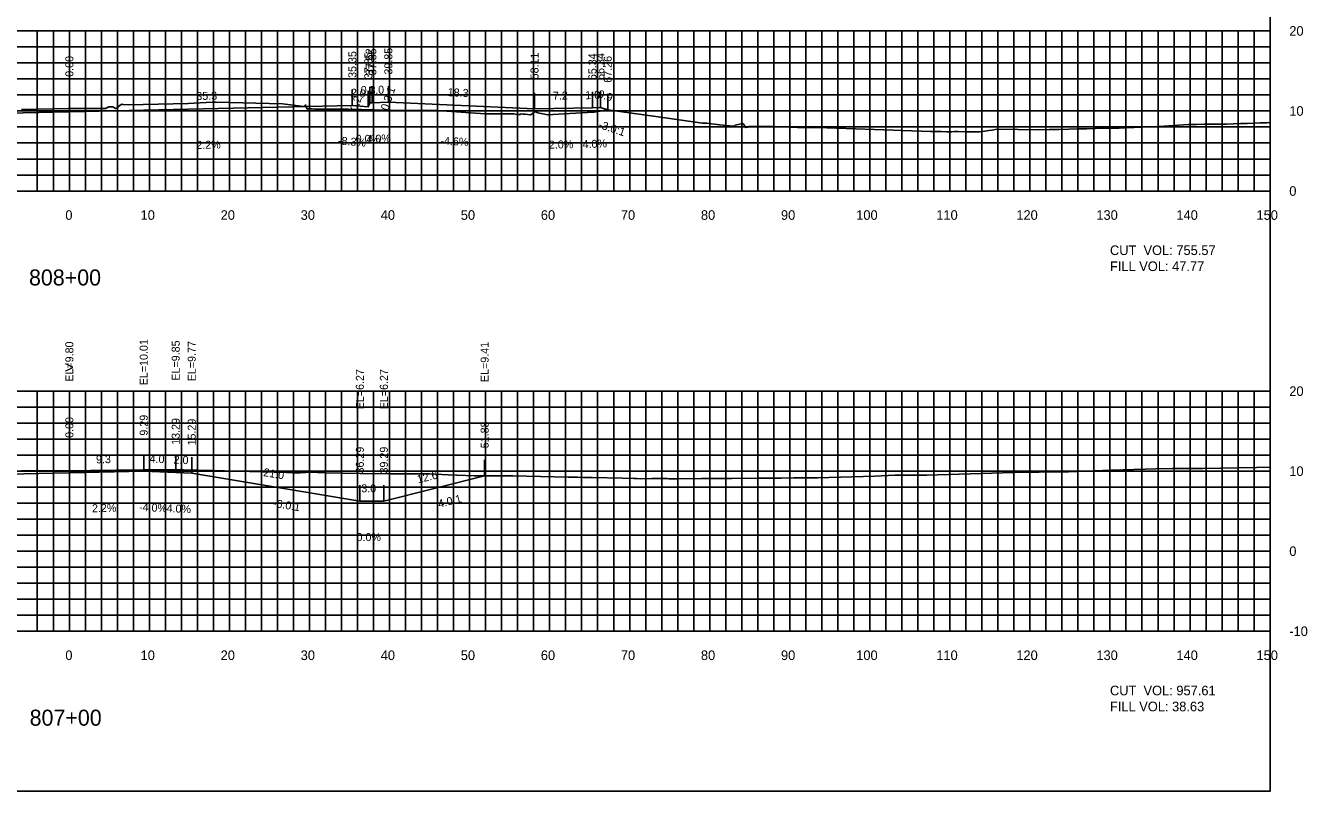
# Model space of a CAD drawing. Extents: x 1797419 to 1809236, y 248759 to 251512.
# Drawn here: x 1803985.5 to 1804145.7, y 250417.3 to 250512.9 of the extents above; entities that cross this region are included whole.
import ezdxf

# ---------------------------------------------------------------- set-up
doc = ezdxf.new("R2010")
doc.units = 0
for name, color, linetype in [('1', 7, 'Continuous'), ('10', 7, 'Continuous'), ('3', 7, 'Continuous'), ('31', 7, 'Continuous'), ('4', 7, 'Continuous'), ('60', 7, 'Continuous'), ('ANNO-TXT', 7, 'Continuous'), ('CL-CNST', 7, 'Continuous'), ('Level 62', 7, 'Continuous'), ('M-ROADS', 7, 'Continuous')]:
    doc.layers.add(name, color=color, linetype=linetype)

msp = doc.modelspace()

# ---------------------------------------------------------------- linework, layer by layer
for p, q in [((1804030.85, 250503.36), (1804030.85, 250505.36)), ((1803991, 250502.17), (1803991, 250504.17)), ((1804026.35, 250502.94), (1804026.35, 250504.94)), ((1804028.35, 250502.78), (1804028.35, 250504.78)), ((1804028.52, 250503.28), (1804028.52, 250505.28)), ((1804028.85, 250503.28), (1804028.85, 250505.28)), ((1804049.11, 250502.51), (1804049.11, 250504.51)), ((1804056.34, 250502.66), (1804056.34, 250504.66)), ((1804057.34, 250502.7), (1804057.34, 250504.7)), ((1804058.26, 250502.39), (1804058.26, 250504.39)), ((1803991, 250457.06), (1803991, 250459.06)), ((1804000.29, 250457.26), (1804000.29, 250459.26)), ((1804004.29, 250457.1), (1804004.29, 250459.1)), ((1804006.29, 250457.02), (1804006.29, 250459.02)), ((1804042.88, 250456.67), (1804042.88, 250458.67)), ((1804027.29, 250453.52), (1804027.29, 250455.52)), ((1804030.29, 250453.52), (1804030.29, 250455.52))]:
    msp.add_line(p, q)
msp.add_lwpolyline([(1803841, 250417.26), (1804141, 250417.26), (1804141, 250607.26), (1803841, 250607.26)], close=True)
at = {"layer": '60'}
for p, q in [((1804141, 250492.26), (1804141, 250512.26)), ((1804141.06, 250512.26), (1804141, 250512.26)), ((1804141.06, 250502.26), (1804141, 250502.26)), ((1803841, 250492.26), (1804141, 250492.26)), ((1803991, 250492.2), (1803991, 250492.26)), ((1804001, 250492.2), (1804001, 250492.26)), ((1804011, 250492.2), (1804011, 250492.26)), ((1804021, 250492.2), (1804021, 250492.26)), ((1804031, 250492.2), (1804031, 250492.26)), ((1804041, 250492.2), (1804041, 250492.26)), ((1804051, 250492.2), (1804051, 250492.26)), ((1804061, 250492.2), (1804061, 250492.26)), ((1804071, 250492.2), (1804071, 250492.26)), ((1804081, 250492.2), (1804081, 250492.26)), ((1804091, 250492.2), (1804091, 250492.26)), ((1804101, 250492.2), (1804101, 250492.26)), ((1804111, 250492.2), (1804111, 250492.26)), ((1804121, 250492.2), (1804121, 250492.26)), ((1804131, 250492.2), (1804131, 250492.26)), ((1804141, 250492.2), (1804141, 250492.26)), ((1804141.06, 250492.26), (1804141, 250492.26)), ((1804141, 250437.26), (1804141, 250467.26)), ((1804141.06, 250467.26), (1804141, 250467.26)), ((1804141.06, 250457.26), (1804141, 250457.26)), ((1804141.06, 250447.26), (1804141, 250447.26)), ((1803841, 250437.26), (1804141, 250437.26)), ((1803991, 250437.2), (1803991, 250437.26)), ((1804001, 250437.2), (1804001, 250437.26)), ((1804011, 250437.2), (1804011, 250437.26)), ((1804021, 250437.2), (1804021, 250437.26)), ((1804031, 250437.2), (1804031, 250437.26)), ((1804041, 250437.2), (1804041, 250437.26)), ((1804051, 250437.2), (1804051, 250437.26)), ((1804061, 250437.2), (1804061, 250437.26)), ((1804071, 250437.2), (1804071, 250437.26)), ((1804081, 250437.2), (1804081, 250437.26)), ((1804091, 250437.2), (1804091, 250437.26)), ((1804101, 250437.2), (1804101, 250437.26)), ((1804111, 250437.2), (1804111, 250437.26)), ((1804121, 250437.2), (1804121, 250437.26)), ((1804131, 250437.2), (1804131, 250437.26)), ((1804141, 250437.2), (1804141, 250437.26)), ((1804141.06, 250437.26), (1804141, 250437.26))]:
    msp.add_line(p, q, dxfattribs=at)
at = {"layer": 'CL-CNST'}
for points in [[(1803897.88, 250503.68), (1803905.42, 250501.17), (1803913.42, 250500.85), (1803913.75, 250500.85), (1803913.91, 250500.35), (1803915.91, 250500.51), (1803991, 250502.17), (1804026.35, 250502.94), (1804028.35, 250502.78), (1804028.52, 250503.28), (1804028.85, 250503.28), (1804030.85, 250503.36), (1804049.11, 250502.51), (1804056.34, 250502.66), (1804057.34, 250502.7), (1804058.26, 250502.39)], [(1803879.92, 250457), (1803900, 250451.98), (1803903, 250451.98), (1803924, 250455.48), (1803926, 250455.56), (1803930, 250455.72), (1803991, 250457.06), (1804000.29, 250457.26), (1804004.29, 250457.1), (1804006.29, 250457.02), (1804027.29, 250453.52), (1804030.29, 250453.52), (1804042.88, 250456.67)]]:
    msp.add_lwpolyline(points, dxfattribs=at)
at = {"layer": 'Level 62'}
for p, q in [((1803841, 250512.26), (1804141, 250512.26)), ((1803987, 250492.26), (1803987, 250512.26)), ((1803989, 250492.26), (1803989, 250512.26)), ((1803991, 250492.26), (1803991, 250512.26)), ((1803993, 250492.26), (1803993, 250512.26)), ((1803995, 250492.26), (1803995, 250512.26)), ((1803997, 250492.26), (1803997, 250512.26)), ((1803999, 250492.26), (1803999, 250512.26)), ((1804001, 250492.26), (1804001, 250512.26)), ((1804003, 250492.26), (1804003, 250512.26)), ((1804005, 250492.26), (1804005, 250512.26)), ((1804007, 250492.26), (1804007, 250512.26)), ((1804009, 250492.26), (1804009, 250512.26)), ((1804011, 250492.26), (1804011, 250512.26)), ((1804013, 250492.26), (1804013, 250512.26)), ((1804015, 250492.26), (1804015, 250512.26)), ((1804017, 250492.26), (1804017, 250512.26)), ((1804019, 250492.26), (1804019, 250512.26)), ((1804021, 250492.26), (1804021, 250512.26)), ((1804023, 250492.26), (1804023, 250512.26)), ((1804025, 250492.26), (1804025, 250512.26)), ((1804027, 250492.26), (1804027, 250512.26)), ((1804029, 250492.26), (1804029, 250512.26)), ((1804031, 250492.26), (1804031, 250512.26)), ((1804033, 250492.26), (1804033, 250512.26)), ((1804035, 250492.26), (1804035, 250512.26)), ((1804037, 250492.26), (1804037, 250512.26)), ((1804039, 250492.26), (1804039, 250512.26)), ((1804041, 250492.26), (1804041, 250512.26)), ((1804043, 250492.26), (1804043, 250512.26)), ((1804045, 250492.26), (1804045, 250512.26)), ((1804047, 250492.26), (1804047, 250512.26)), ((1804049, 250492.26), (1804049, 250512.26)), ((1804051, 250492.26), (1804051, 250512.26)), ((1804053, 250492.26), (1804053, 250512.26)), ((1804055, 250492.26), (1804055, 250512.26)), ((1804057, 250492.26), (1804057, 250512.26)), ((1804059, 250492.26), (1804059, 250512.26)), ((1804061, 250492.26), (1804061, 250512.26)), ((1804063, 250492.26), (1804063, 250512.26)), ((1804065, 250492.26), (1804065, 250512.26)), ((1804067, 250492.26), (1804067, 250512.26)), ((1804069, 250492.26), (1804069, 250512.26)), ((1804071, 250492.26), (1804071, 250512.26)), ((1804073, 250492.26), (1804073, 250512.26)), ((1804075, 250492.26), (1804075, 250512.26)), ((1804077, 250492.26), (1804077, 250512.26)), ((1804079, 250492.26), (1804079, 250512.26)), ((1804081, 250492.26), (1804081, 250512.26)), ((1804083, 250492.26), (1804083, 250512.26)), ((1804085, 250492.26), (1804085, 250512.26)), ((1804087, 250492.26), (1804087, 250512.26)), ((1804089, 250492.26), (1804089, 250512.26)), ((1804091, 250492.26), (1804091, 250512.26)), ((1804093, 250492.26), (1804093, 250512.26)), ((1804095, 250492.26), (1804095, 250512.26)), ((1804097, 250492.26), (1804097, 250512.26)), ((1804099, 250492.26), (1804099, 250512.26)), ((1804101, 250492.26), (1804101, 250512.26)), ((1804103, 250492.26), (1804103, 250512.26)), ((1804105, 250492.26), (1804105, 250512.26)), ((1804107, 250492.26), (1804107, 250512.26)), ((1804109, 250492.26), (1804109, 250512.26)), ((1804111, 250492.26), (1804111, 250512.26)), ((1804113, 250492.26), (1804113, 250512.26)), ((1804115, 250492.26), (1804115, 250512.26)), ((1804117, 250492.26), (1804117, 250512.26)), ((1804119, 250492.26), (1804119, 250512.26)), ((1804121, 250492.26), (1804121, 250512.26)), ((1804123, 250492.26), (1804123, 250512.26)), ((1804125, 250492.26), (1804125, 250512.26)), ((1804127, 250492.26), (1804127, 250512.26)), ((1804129, 250492.26), (1804129, 250512.26)), ((1804131, 250492.26), (1804131, 250512.26)), ((1804133, 250492.26), (1804133, 250512.26)), ((1804135, 250492.26), (1804135, 250512.26)), ((1804137, 250492.26), (1804137, 250512.26)), ((1804139, 250492.26), (1804139, 250512.26)), ((1804141, 250492.26), (1804141, 250512.26)), ((1803841, 250510.26), (1804141, 250510.26)), ((1803841, 250508.26), (1804141, 250508.26)), ((1803841, 250506.26), (1804141, 250506.26)), ((1803841, 250504.26), (1804141, 250504.26)), ((1803841, 250502.26), (1804141, 250502.26)), ((1803841, 250500.26), (1804141, 250500.26)), ((1803841, 250498.26), (1804141, 250498.26)), ((1803841, 250496.26), (1804141, 250496.26)), ((1803841, 250494.26), (1804141, 250494.26)), ((1803841, 250492.26), (1804141, 250492.26)), ((1803841, 250467.26), (1804141, 250467.26)), ((1803987, 250437.26), (1803987, 250467.26)), ((1803989, 250437.26), (1803989, 250467.26)), ((1803991, 250437.26), (1803991, 250467.26)), ((1803993, 250437.26), (1803993, 250467.26)), ((1803995, 250437.26), (1803995, 250467.26)), ((1803997, 250437.26), (1803997, 250467.26)), ((1803999, 250437.26), (1803999, 250467.26)), ((1804001, 250437.26), (1804001, 250467.26)), ((1804003, 250437.26), (1804003, 250467.26)), ((1804005, 250437.26), (1804005, 250467.26)), ((1804007, 250437.26), (1804007, 250467.26)), ((1804009, 250437.26), (1804009, 250467.26)), ((1804011, 250437.26), (1804011, 250467.26)), ((1804013, 250437.26), (1804013, 250467.26)), ((1804015, 250437.26), (1804015, 250467.26)), ((1804017, 250437.26), (1804017, 250467.26)), ((1804019, 250437.26), (1804019, 250467.26)), ((1804021, 250437.26), (1804021, 250467.26)), ((1804023, 250437.26), (1804023, 250467.26)), ((1804025, 250437.26), (1804025, 250467.26)), ((1804027, 250437.26), (1804027, 250467.26)), ((1804029, 250437.26), (1804029, 250467.26)), ((1804031, 250437.26), (1804031, 250467.26)), ((1804033, 250437.26), (1804033, 250467.26)), ((1804035, 250437.26), (1804035, 250467.26)), ((1804037, 250437.26), (1804037, 250467.26)), ((1804039, 250437.26), (1804039, 250467.26)), ((1804041, 250437.26), (1804041, 250467.26)), ((1804043, 250437.26), (1804043, 250467.26)), ((1804045, 250437.26), (1804045, 250467.26)), ((1804047, 250437.26), (1804047, 250467.26)), ((1804049, 250437.26), (1804049, 250467.26)), ((1804051, 250437.26), (1804051, 250467.26)), ((1804053, 250437.26), (1804053, 250467.26)), ((1804055, 250437.26), (1804055, 250467.26)), ((1804057, 250437.26), (1804057, 250467.26)), ((1804059, 250437.26), (1804059, 250467.26)), ((1804061, 250437.26), (1804061, 250467.26)), ((1804063, 250437.26), (1804063, 250467.26)), ((1804065, 250437.26), (1804065, 250467.26)), ((1804067, 250437.26), (1804067, 250467.26)), ((1804069, 250437.26), (1804069, 250467.26)), ((1804071, 250437.26), (1804071, 250467.26)), ((1804073, 250437.26), (1804073, 250467.26)), ((1804075, 250437.26), (1804075, 250467.26)), ((1804077, 250437.26), (1804077, 250467.26)), ((1804079, 250437.26), (1804079, 250467.26)), ((1804081, 250437.26), (1804081, 250467.26)), ((1804083, 250437.26), (1804083, 250467.26)), ((1804085, 250437.26), (1804085, 250467.26)), ((1804087, 250437.26), (1804087, 250467.26)), ((1804089, 250437.26), (1804089, 250467.26)), ((1804091, 250437.26), (1804091, 250467.26)), ((1804093, 250437.26), (1804093, 250467.26)), ((1804095, 250437.26), (1804095, 250467.26)), ((1804097, 250437.26), (1804097, 250467.26)), ((1804099, 250437.26), (1804099, 250467.26)), ((1804101, 250437.26), (1804101, 250467.26)), ((1804103, 250437.26), (1804103, 250467.26)), ((1804105, 250437.26), (1804105, 250467.26)), ((1804107, 250437.26), (1804107, 250467.26)), ((1804109, 250437.26), (1804109, 250467.26)), ((1804111, 250437.26), (1804111, 250467.26)), ((1804113, 250437.26), (1804113, 250467.26)), ((1804115, 250437.26), (1804115, 250467.26)), ((1804117, 250437.26), (1804117, 250467.26)), ((1804119, 250437.26), (1804119, 250467.26)), ((1804121, 250437.26), (1804121, 250467.26)), ((1804123, 250437.26), (1804123, 250467.26)), ((1804125, 250437.26), (1804125, 250467.26)), ((1804127, 250437.26), (1804127, 250467.26)), ((1804129, 250437.26), (1804129, 250467.26)), ((1804131, 250437.26), (1804131, 250467.26)), ((1804133, 250437.26), (1804133, 250467.26)), ((1804135, 250437.26), (1804135, 250467.26)), ((1804137, 250437.26), (1804137, 250467.26)), ((1804139, 250437.26), (1804139, 250467.26)), ((1804141, 250437.26), (1804141, 250467.26)), ((1803841, 250465.26), (1804141, 250465.26)), ((1803841, 250463.26), (1804141, 250463.26)), ((1803841, 250461.26), (1804141, 250461.26)), ((1803841, 250459.26), (1804141, 250459.26)), ((1803841, 250457.26), (1804141, 250457.26)), ((1803841, 250455.26), (1804141, 250455.26)), ((1803841, 250453.26), (1804141, 250453.26)), ((1803841, 250451.26), (1804141, 250451.26)), ((1803841, 250449.26), (1804141, 250449.26)), ((1803841, 250447.26), (1804141, 250447.26)), ((1803841, 250445.26), (1804141, 250445.26)), ((1803841, 250443.26), (1804141, 250443.26)), ((1803841, 250441.26), (1804141, 250441.26)), ((1803841, 250439.26), (1804141, 250439.26)), ((1803841, 250437.26), (1804141, 250437.26))]:
    msp.add_line(p, q, dxfattribs=at)
at = {"layer": 'M-ROADS'}
for points in [[(1803985.03, 250502.46), (1803990.87, 250502.56), (1803992.17, 250502.59), (1803993.13, 250502.58), (1803993.36, 250502.58), (1803994.16, 250502.59), (1803994.44, 250502.59), (1803994.55, 250502.59), (1803995.52, 250502.58), (1803995.92, 250502.79), (1803996.43, 250502.78), (1803996.78, 250502.59), (1803996.85, 250502.6), (1803996.87, 250502.6), (1803996.88, 250502.61), (1803996.9, 250502.61), (1803996.99, 250502.68), (1803997.48, 250503.06), (1803997.55, 250503.12), (1803997.68, 250503.08), (1803998.34, 250503.03), (1804005.85, 250503.21), (1804008.84, 250503.38), (1804008.97, 250503.38), (1804009.33, 250503.38), (1804017.63, 250503.14), (1804020.29, 250502.83), (1804020.52, 250503.01), (1804020.65, 250502.56), (1804020.72, 250502.5), (1804021.03, 250502.61), (1804021.08, 250502.54), (1804021.19, 250502.53), (1804021.22, 250502.53), (1804021.26, 250502.52), (1804021.35, 250502.51), (1804021.57, 250502.49), (1804021.66, 250502.49), (1804021.87, 250502.49), (1804022.41, 250502.5), (1804023.07, 250502.5), (1804023.77, 250502.49), (1804023.94, 250502.49), (1804024.71, 250502.5), (1804025.11, 250502.49), (1804025.73, 250502.49), (1804025.87, 250502.5), (1804030.76, 250502.35), (1804032.62, 250502.3), (1804032.67, 250502.3), (1804032.73, 250502.3), (1804033.51, 250502.31), (1804033.71, 250502.31), (1804034.82, 250502.3), (1804035.33, 250502.3), (1804036.11, 250502.3), (1804036.57, 250502.3), (1804036.95, 250502.31), (1804042.95, 250501.92), (1804043.1, 250501.91), (1804043.26, 250501.91), (1804043.93, 250501.92), (1804044.03, 250501.91), (1804045.24, 250501.91), (1804045.62, 250501.91), (1804046.54, 250501.91), (1804046.92, 250501.84), (1804047.35, 250501.84), (1804047.37, 250501.92), (1804047.65, 250501.88), (1804047.94, 250501.85), (1804048.61, 250501.77), (1804048.62, 250501.77), (1804048.8, 250501.91), (1804049.17, 250502.21), (1804049.51, 250502.01), (1804050.77, 250501.78), (1804050.82, 250501.78), (1804051.41, 250501.81), (1804056.41, 250502.11), (1804056.47, 250502.11), (1804056.5, 250502.1), (1804056.51, 250502.11), (1804056.58, 250502.11), (1804058.27, 250502.39), (1804064.26, 250501.56), (1804070.1, 250500.72), (1804070.62, 250500.73), (1804071.22, 250500.65), (1804072.25, 250500.54), (1804073.94, 250500.36), (1804073.97, 250500.37), (1804074.09, 250500.42), (1804074.18, 250500.5), (1804075.11, 250500.71), (1804075.25, 250500.58), (1804075.45, 250500.19), (1804075.68, 250500.22), (1804075.72, 250500.21), (1804075.77, 250500.26), (1804075.84, 250500.27), (1804075.92, 250500.31), (1804075.92, 250500.31), (1804075.94, 250500.31), (1804075.98, 250500.31), (1804076.8, 250500.33), (1804077.1, 250500.36), (1804078.25, 250500.33), (1804079.09, 250500.31), (1804080.06, 250500.27), (1804081.95, 250500.21), (1804083.79, 250500.21), (1804084.47, 250500.21), (1804091.58, 250499.95), (1804096.26, 250499.78), (1804098.59, 250499.7), (1804099.95, 250499.71), (1804100.61, 250499.66), (1804101.23, 250499.67), (1804101.58, 250499.68), (1804102.04, 250499.71), (1804102.91, 250499.66), (1804104.68, 250499.66), (1804104.73, 250499.66), (1804105.35, 250499.75), (1804105.86, 250499.84), (1804106.28, 250499.88), (1804106.64, 250499.93), (1804106.95, 250499.97), (1804112.12, 250499.91), (1804113.41, 250499.94), (1804114.65, 250499.95), (1804115.84, 250499.98), (1804116.99, 250500.01), (1804118.1, 250500.04), (1804119.17, 250500.08), (1804120.2, 250500.11), (1804121.19, 250500.12), (1804122.15, 250500.13), (1804123.08, 250500.15), (1804123.98, 250500.19), (1804124.84, 250500.23), (1804125.68, 250500.26), (1804126.49, 250500.28), (1804130.79, 250500.55), (1804131.79, 250500.57), (1804132.77, 250500.6), (1804133.73, 250500.6), (1804134.66, 250500.6), (1804135.56, 250500.62), (1804136.45, 250500.65), (1804137.31, 250500.69), (1804138.15, 250500.71), (1804138.97, 250500.75), (1804139.78, 250500.77), (1804140.56, 250500.79), (1804141, 250500.8)], [(1803985, 250457.3), (1803986.31, 250457.3), (1803986.75, 250457.3), (1803987.53, 250457.3), (1803987.59, 250457.3), (1803987.62, 250457.3), (1803987.79, 250457.3), (1803989.39, 250457.3), (1803990.37, 250457.32), (1804000.18, 250457.43), (1804000.37, 250457.44), (1804000.76, 250457.44), (1804002.15, 250457.42), (1804002.42, 250457.42), (1804003.15, 250457.44), (1804003.43, 250457.43), (1804003.84, 250457.44), (1804005.21, 250457.44), (1804008.85, 250457.35), (1804018.11, 250457.1), (1804019.03, 250457.06), (1804019.89, 250457.04), (1804020.53, 250457.08), (1804020.54, 250457.09), (1804021.18, 250457.13), (1804022.02, 250457.11), (1804022.95, 250457.07), (1804027.32, 250456.98), (1804031.15, 250456.92), (1804032.74, 250456.92), (1804032.89, 250456.93), (1804033.05, 250456.92), (1804033.74, 250456.91), (1804034.22, 250456.91), (1804035.39, 250456.92), (1804035.98, 250456.92), (1804038.34, 250456.81), (1804041.6, 250456.68), (1804042.45, 250456.67), (1804043.32, 250456.67), (1804043.92, 250456.68), (1804044.32, 250456.68), (1804044.66, 250456.68), (1804044.99, 250456.68), (1804046.42, 250456.67), (1804053.33, 250456.53), (1804054.5, 250456.5), (1804055.19, 250456.48), (1804055.32, 250456.48), (1804056.31, 250456.46), (1804060.09, 250456.38), (1804061.5, 250456.35), (1804061.6, 250456.35), (1804061.61, 250456.34), (1804061.88, 250456.34), (1804062.38, 250456.32), (1804063.75, 250456.33), (1804065.24, 250456.34), (1804065.69, 250456.33), (1804065.91, 250456.32), (1804066.9, 250456.32), (1804069.99, 250456.36), (1804071.54, 250456.35), (1804072.77, 250456.35), (1804073.77, 250456.36), (1804077.07, 250456.38), (1804077.73, 250456.39), (1804078.25, 250456.39), (1804079.97, 250456.39), (1804081.51, 250456.43), (1804084.46, 250456.44), (1804091.61, 250456.65), (1804094.13, 250456.75), (1804095.42, 250456.75), (1804098.02, 250456.75), (1804098.07, 250456.74), (1804098.11, 250456.75), (1804110.28, 250457.14), (1804112.15, 250457.14), (1804114.67, 250457.18), (1804115.8, 250457.18), (1804121.21, 250457.39), (1804125.39, 250457.5), (1804126.7, 250457.54), (1804128.77, 250457.59), (1804129.13, 250457.59), (1804132.6, 250457.58), (1804139.29, 250457.72), (1804141, 250457.75)]]:
    msp.add_lwpolyline(points, dxfattribs=at)

# ---------------------------------------------------------------- texts
for s, rotation, p in [('0.3:1', 71.5647, (1804030.81, 250502.24)), ('-3.0:1', 341.5651, (1804057.01, 250500.17)), ('4.0:1', 14.0362, (1804037.19, 250452.67)), ('-6.0:1', 350.5377, (1804016.38, 250452.81))]:
    msp.add_text(s, height=1, rotation=rotation).set_placement(p)
at = {"layer": '1'}
for s, p in [('808+00', (1803985.96, 250480.46)), ('807+00', (1803986.04, 250425.46))]:
    msp.add_text(s, height=2, dxfattribs=at).set_placement(p)
at = {"layer": '10'}
for s, p in [('0', (1803990.5, 250488.66)), ('10', (1803999.9, 250488.66)), ('20', (1804009.9, 250488.66)), ('30', (1804019.9, 250488.66)), ('40', (1804029.9, 250488.66)), ('50', (1804039.9, 250488.66)), ('60', (1804049.9, 250488.66)), ('70', (1804059.9, 250488.66)), ('80', (1804069.9, 250488.66)), ('90', (1804079.9, 250488.66)), ('100', (1804089.3, 250488.66)), ('110', (1804099.3, 250488.66)), ('120', (1804109.3, 250488.66)), ('130', (1804119.3, 250488.66)), ('140', (1804129.3, 250488.66)), ('150', (1804139.3, 250488.66)), ('0', (1803990.5, 250433.66)), ('10', (1803999.9, 250433.66)), ('20', (1804009.9, 250433.66)), ('30', (1804019.9, 250433.66)), ('40', (1804029.9, 250433.66)), ('50', (1804039.9, 250433.66)), ('60', (1804049.9, 250433.66)), ('70', (1804059.9, 250433.66)), ('80', (1804069.9, 250433.66)), ('90', (1804079.9, 250433.66)), ('100', (1804089.3, 250433.66)), ('110', (1804099.3, 250433.66)), ('120', (1804109.3, 250433.66)), ('130', (1804119.3, 250433.66)), ('140', (1804129.3, 250433.66)), ('150', (1804139.3, 250433.66))]:
    msp.add_text(s, height=1.2, dxfattribs=at).set_placement(p)
at = {"layer": '3'}
for s, p in [('0.00', (1803991.5, 250506.53)), ('35.35', (1804026.85, 250506.39)), ('37.35', (1804028.85, 250506.23)), ('37.52', (1804029.02, 250506.73)), ('37.85', (1804029.35, 250506.73)), ('39.85', (1804031.35, 250506.81)), ('58.11', (1804049.61, 250506.21)), ('65.34', (1804056.84, 250506.11)), ('66.34', (1804057.84, 250506.15)), ('67.26', (1804058.76, 250505.79)), ('EL=9.80', (1803991.5, 250468.44)), ('EL=10.01', (1804000.79, 250467.99)), ('EL=9.85', (1804004.79, 250468.57)), ('EL=9.77', (1804006.79, 250468.49)), ('EL=9.41', (1804043.38, 250468.39)), ('EL=6.27', (1804027.79, 250464.99)), ('EL=6.27', (1804030.79, 250464.99)), ('0.00', (1803991.5, 250461.42)), ('9.29', (1804000.79, 250461.7)), ('13.29', (1804004.79, 250460.55)), ('15.29', (1804006.79, 250460.47)), ('51.88', (1804043.38, 250460.12)), ('36.29', (1804027.79, 250456.97)), ('39.29', (1804030.79, 250456.97))]:
    msp.add_text(s, height=1, rotation=90, dxfattribs=at).set_placement(p)
at = {"layer": '31'}
for s, p in [('20', (1804143.4, 250511.66)), ('10', (1804143.4, 250501.66)), ('0', (1804143.4, 250491.66)), ('20', (1804143.4, 250466.66)), ('10', (1804143.4, 250456.66)), ('0', (1804143.4, 250446.66)), ('-10', (1804143.4, 250436.66))]:
    msp.add_text(s, height=1.2, dxfattribs=at).set_placement(p)
at = {"layer": '4'}
for s, p in [('0.3', (1804027.4, 250504.38)), ('0.0%', (1804026.77, 250498.28)), ('3.0', (1804027.47, 250454.62)), ('0.0%', (1804026.88, 250448.52))]:
    msp.add_text(s, height=1, dxfattribs=at).set_placement(p)
for s, rotation, p in [('2.0', 2.2906, (1804028.48, 250504.36)), ('35.3', 1.2603, (1804006.87, 250503.62)), ('0.2', 71.5647, (1804026.98, 250502.16)), ('2.0', 355.2364, (1804026.12, 250504.07)), ('18.3', 357.3503, (1804038.25, 250504.12)), ('7.2', 1.1458, (1804051.42, 250503.66)), ('1.0', 2.2906, (1804055.47, 250503.72)), ('0.9', 341.5651, (1804056.93, 250503.99)), ('-8.3%', 355.2364, (1804024.53, 250498.08)), ('4.0%', 2.2906, (1804028.14, 250498.24)), ('-4.6%', 357.3503, (1804037.34, 250498.05)), ('2.2%', 1.2603, (1804006.87, 250497.51)), ('2.0%', 1.1458, (1804050.91, 250497.55)), ('4.0%', 2.2906, (1804055.13, 250497.6)), ('9.3', 1.2603, (1803994.34, 250458.23)), ('4.0', 357.7094, (1804001.01, 250458.33)), ('2.0', 357.7094, (1804004.01, 250458.21)), ('21.0', 350.5377, (1804015.18, 250456.66)), ('12.6', 14.0362, (1804034.57, 250455.73)), ('2.2%', 1.2603, (1803993.84, 250452.12)), ('-4.0%', 357.7094, (1803999.69, 250452.28)), ('-4.0%', 357.7094, (1804002.69, 250452.16))]:
    msp.add_text(s, height=1, rotation=rotation, dxfattribs=at).set_placement(p)
at = {"layer": '60'}
msp.add_text('>', height=1.5, dxfattribs=at).set_placement((1803990.39, 250469.51))
at = {"layer": 'ANNO-TXT'}
for s, p in [('CUT  VOL: 755.57', (1804121, 250484.26)), ('FILL VOL: 47.77', (1804121, 250482.26)), ('CUT  VOL: 957.61', (1804121, 250429.26)), ('FILL VOL: 38.63', (1804121, 250427.26))]:
    msp.add_text(s, height=1.2, dxfattribs=at).set_placement(p)

doc.saveas('drawing.dxf')
